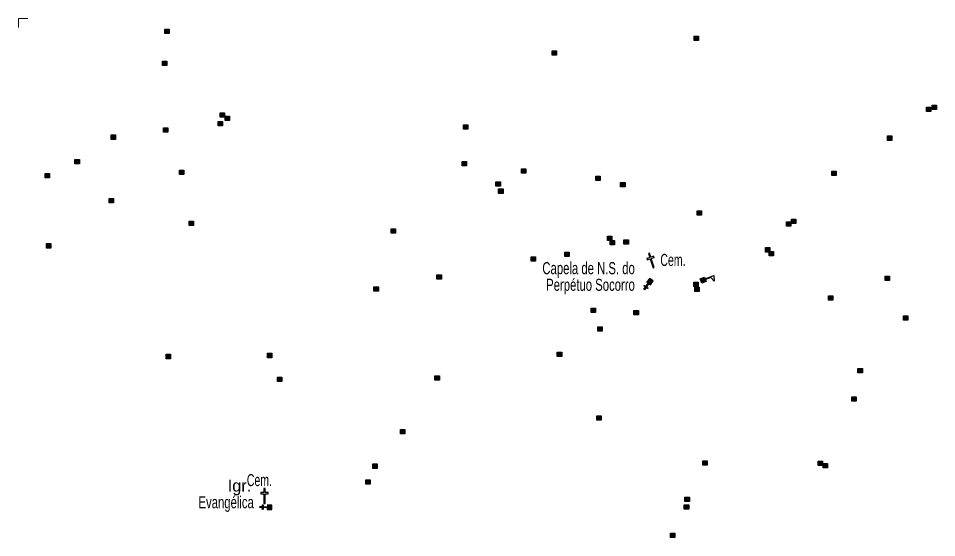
# Model space of a CAD drawing. Extents: x 647.8 to 672.9, y 6929.3 to 6957.3.
# Drawn here: x 648.17 to 654.25, y 6953.84 to 6957.28 of the extents above; entities that cross this region are included whole.
import ezdxf
from ezdxf.enums import TextEntityAlignment as Align

# ---------------------------------------------------------------- set-up
doc = ezdxf.new("R2010")
doc.units = 0
doc.header["$LTSCALE"] = 0.032
for name, color, linetype, lineweight in [('2', 7, 'Continuous', 25), ('20', 7, 'Continuous', 25), ('4', 7, 'Continuous', 25), ('6', 7, 'Continuous', 25), ('63', 7, 'Continuous', 13)]:
    doc.layers.add(name, color=color, linetype=linetype, lineweight=lineweight)
doc.layers.add('61', color=7, linetype='Continuous')

msp = doc.modelspace()

# ---------------------------------------------------------------- hatches: boundary and pattern name
at = {"layer": '2'}
for points in [[(649.1381, 6957.206), (649.1671, 6957.206), (649.1671, 6957.177), (649.1381, 6957.177)], [(652.6417, 6957.1599), (652.6707, 6957.1599), (652.6707, 6957.1309), (652.6417, 6957.1309)], [(651.7005, 6957.0634), (651.7295, 6957.0634), (651.7295, 6957.0344), (651.7005, 6957.0344)], [(649.1228, 6956.9954), (649.1518, 6956.9954), (649.1518, 6956.9664), (649.1228, 6956.9664)], [(649.5045, 6956.6531), (649.5335, 6956.6531), (649.5335, 6956.6241), (649.5045, 6956.6241)], [(654.1796, 6956.6904), (654.2086, 6956.6904), (654.2086, 6956.6614), (654.1796, 6956.6614)], [(654.2169, 6956.7036), (654.2459, 6956.7036), (654.2459, 6956.6746), (654.2169, 6956.6746)], [(649.4913, 6956.5961), (649.5203, 6956.5961), (649.5203, 6956.5671), (649.4913, 6956.5671)], [(649.5374, 6956.6312), (649.5664, 6956.6312), (649.5664, 6956.6022), (649.5374, 6956.6022)], [(649.1294, 6956.5544), (649.1584, 6956.5544), (649.1584, 6956.5254), (649.1294, 6956.5254)], [(651.1148, 6956.5742), (651.1438, 6956.5742), (651.1438, 6956.5452), (651.1148, 6956.5452)], [(648.7827, 6956.5061), (648.8117, 6956.5061), (648.8117, 6956.4771), (648.7827, 6956.4771)], [(653.9207, 6956.4996), (653.9497, 6956.4996), (653.9497, 6956.4706), (653.9207, 6956.4706)], [(648.5436, 6956.3438), (648.5726, 6956.3438), (648.5726, 6956.3148), (648.5436, 6956.3148)], [(651.106, 6956.3306), (651.135, 6956.3306), (651.135, 6956.3016), (651.106, 6956.3016)], [(651.4987, 6956.2824), (651.5277, 6956.2824), (651.5277, 6956.2534), (651.4987, 6956.2534)], [(648.3462, 6956.2517), (648.3752, 6956.2517), (648.3752, 6956.2227), (648.3462, 6956.2227)], [(649.2347, 6956.2736), (649.2637, 6956.2736), (649.2637, 6956.2446), (649.2347, 6956.2446)], [(651.9901, 6956.2341), (652.0191, 6956.2341), (652.0191, 6956.2051), (651.9901, 6956.2051)], [(653.5521, 6956.267), (653.5811, 6956.267), (653.5811, 6956.238), (653.5521, 6956.238)], [(651.3298, 6956.1968), (651.3588, 6956.1968), (651.3588, 6956.1678), (651.3298, 6956.1678)], [(652.1547, 6956.1924), (652.1837, 6956.1924), (652.1837, 6956.1634), (652.1547, 6956.1634)], [(651.3473, 6956.1485), (651.3763, 6956.1485), (651.3763, 6956.1195), (651.3473, 6956.1195)], [(648.7696, 6956.0849), (648.7986, 6956.0849), (648.7986, 6956.0559), (648.7696, 6956.0559)], [(652.6614, 6956.0038), (652.6904, 6956.0038), (652.6904, 6955.9748), (652.6614, 6955.9748)], [(649.2983, 6955.9357), (649.3273, 6955.9357), (649.3273, 6955.9067), (649.2983, 6955.9067)], [(653.2516, 6955.9314), (653.2806, 6955.9314), (653.2806, 6955.9024), (653.2516, 6955.9024)], [(653.2845, 6955.9489), (653.3135, 6955.9489), (653.3135, 6955.9199), (653.2845, 6955.9199)], [(650.6365, 6955.8853), (650.6655, 6955.8853), (650.6655, 6955.8563), (650.6365, 6955.8563)], [(652.0669, 6955.837), (652.0959, 6955.837), (652.0959, 6955.808), (652.0669, 6955.808)], [(652.0845, 6955.8085), (652.1135, 6955.8085), (652.1135, 6955.7795), (652.0845, 6955.7795)], [(652.1766, 6955.8129), (652.2056, 6955.8129), (652.2056, 6955.7839), (652.1766, 6955.7839)], [(648.3549, 6955.7866), (648.3839, 6955.7866), (648.3839, 6955.7576), (648.3549, 6955.7576)], [(653.1134, 6955.7602), (653.1424, 6955.7602), (653.1424, 6955.7312), (653.1134, 6955.7312)], [(651.5623, 6955.6988), (651.5913, 6955.6988), (651.5913, 6955.6698), (651.5623, 6955.6698)], [(651.7861, 6955.7295), (651.8151, 6955.7295), (651.8151, 6955.7005), (651.7861, 6955.7005)], [(653.1375, 6955.7339), (653.1665, 6955.7339), (653.1665, 6955.7049), (653.1375, 6955.7049)], [(650.9393, 6955.5803), (650.9683, 6955.5803), (650.9683, 6955.5513), (650.9393, 6955.5513)], [(653.9054, 6955.5716), (653.9344, 6955.5716), (653.9344, 6955.5426), (653.9054, 6955.5426)], [(650.5224, 6955.5014), (650.5514, 6955.5014), (650.5514, 6955.4724), (650.5224, 6955.4724)], [(652.6395, 6955.5321), (652.6685, 6955.5321), (652.6685, 6955.5031), (652.6395, 6955.5031)], [(652.6461, 6955.4992), (652.6751, 6955.4992), (652.6751, 6955.4702), (652.6461, 6955.4702)], [(653.5302, 6955.4421), (653.5592, 6955.4421), (653.5592, 6955.4131), (653.5302, 6955.4131)], [(651.9594, 6955.3588), (651.9884, 6955.3588), (651.9884, 6955.3298), (651.9594, 6955.3298)], [(652.243, 6955.3448), (652.272, 6955.3448), (652.272, 6955.3158), (652.243, 6955.3158)], [(654.026, 6955.3083), (654.055, 6955.3083), (654.055, 6955.2793), (654.026, 6955.2793)], [(652.0033, 6955.2359), (652.0323, 6955.2359), (652.0323, 6955.2069), (652.0033, 6955.2069)], [(651.7356, 6955.0692), (651.7646, 6955.0692), (651.7646, 6955.0402), (651.7356, 6955.0402)], [(649.1469, 6955.0538), (649.1759, 6955.0538), (649.1759, 6955.0248), (649.1469, 6955.0248)], [(649.8182, 6955.0604), (649.8472, 6955.0604), (649.8472, 6955.0314), (649.8182, 6955.0314)], [(653.7255, 6954.9595), (653.7545, 6954.9595), (653.7545, 6954.9305), (653.7255, 6954.9305)], [(649.884, 6954.9024), (649.913, 6954.9024), (649.913, 6954.8734), (649.884, 6954.8734)], [(650.9261, 6954.9112), (650.9551, 6954.9112), (650.9551, 6954.8822), (650.9261, 6954.8822)], [(653.6838, 6954.773), (653.7128, 6954.773), (653.7128, 6954.744), (653.6838, 6954.744)], [(651.9967, 6954.6458), (652.0257, 6954.6458), (652.0257, 6954.6168), (651.9967, 6954.6168)], [(650.698, 6954.5558), (650.727, 6954.5558), (650.727, 6954.5268), (650.698, 6954.5268)], [(652.6987, 6954.3496), (652.7277, 6954.3496), (652.7277, 6954.3206), (652.6987, 6954.3206)], [(653.4622, 6954.3474), (653.4912, 6954.3474), (653.4912, 6954.3184), (653.4622, 6954.3184)], [(650.5137, 6954.3277), (650.5427, 6954.3277), (650.5427, 6954.2987), (650.5137, 6954.2987)], [(653.4951, 6954.332), (653.5241, 6954.332), (653.5241, 6954.303), (653.4951, 6954.303)], [(650.4676, 6954.2224), (650.4966, 6954.2224), (650.4966, 6954.1934), (650.4676, 6954.1934)], [(652.5803, 6954.1083), (652.6093, 6954.1083), (652.6093, 6954.0793), (652.5803, 6954.0793)], [(652.5759, 6954.0578), (652.6049, 6954.0578), (652.6049, 6954.0288), (652.5759, 6954.0288)], [(652.4837, 6953.8691), (652.5127, 6953.8691), (652.5127, 6953.8401), (652.4837, 6953.8401)]]:
    msp.add_hatch(color=256, dxfattribs=at).paths.add_polyline_path(points)
at = {"layer": '4'}
msp.add_hatch(color=256, dxfattribs=at).paths.add_polyline_path([(652.6812, 6955.5538), (652.7091, 6955.5649), (652.7202, 6955.537), (652.6923, 6955.5259)])
at = {"layer": '6'}
for points in [[(652.352, 6955.515), (652.3696, 6955.5393), (652.3453, 6955.5568), (652.3277, 6955.5325)], [(652.3379, 6955.5252), (652.3419, 6955.5223), (652.3258, 6955.5), (652.3359, 6955.4927), (652.333, 6955.4886), (652.3229, 6955.4959), (652.3126, 6955.4818), (652.3086, 6955.4847), (652.3188, 6955.4989), (652.3087, 6955.5062), (652.3116, 6955.5102), (652.3217, 6955.5029)], [(649.8164, 6954.0442), (649.8162, 6954.0392), (649.7888, 6954.04), (649.7884, 6954.0275), (649.7834, 6954.0277), (649.7838, 6954.0402), (649.7663, 6954.0406), (649.7664, 6954.0456), (649.7839, 6954.0452), (649.7842, 6954.0576), (649.7892, 6954.0575), (649.7889, 6954.045)], [(649.8159, 6954.0268), (649.8459, 6954.0259), (649.8467, 6954.0559), (649.8167, 6954.0567)]]:
    msp.add_hatch(color=256, dxfattribs=at).paths.add_polyline_path(points)

# ---------------------------------------------------------------- linework, layer by layer
at = {"layer": '2'}
for points in [[(649.1381, 6957.206), (649.1671, 6957.206), (649.1671, 6957.177), (649.1381, 6957.177)], [(652.6417, 6957.1599), (652.6707, 6957.1599), (652.6707, 6957.1309), (652.6417, 6957.1309)], [(651.7005, 6957.0634), (651.7295, 6957.0634), (651.7295, 6957.0344), (651.7005, 6957.0344)], [(649.1228, 6956.9954), (649.1518, 6956.9954), (649.1518, 6956.9664), (649.1228, 6956.9664)], [(649.5045, 6956.6531), (649.5335, 6956.6531), (649.5335, 6956.6241), (649.5045, 6956.6241)], [(654.1796, 6956.6904), (654.2086, 6956.6904), (654.2086, 6956.6614), (654.1796, 6956.6614)], [(654.2169, 6956.7036), (654.2459, 6956.7036), (654.2459, 6956.6746), (654.2169, 6956.6746)], [(649.4913, 6956.5961), (649.5203, 6956.5961), (649.5203, 6956.5671), (649.4913, 6956.5671)], [(649.5374, 6956.6312), (649.5664, 6956.6312), (649.5664, 6956.6022), (649.5374, 6956.6022)], [(649.1294, 6956.5544), (649.1584, 6956.5544), (649.1584, 6956.5254), (649.1294, 6956.5254)], [(651.1148, 6956.5742), (651.1438, 6956.5742), (651.1438, 6956.5452), (651.1148, 6956.5452)], [(648.7827, 6956.5061), (648.8117, 6956.5061), (648.8117, 6956.4771), (648.7827, 6956.4771)], [(653.9207, 6956.4996), (653.9497, 6956.4996), (653.9497, 6956.4706), (653.9207, 6956.4706)], [(648.5436, 6956.3438), (648.5726, 6956.3438), (648.5726, 6956.3148), (648.5436, 6956.3148)], [(651.106, 6956.3306), (651.135, 6956.3306), (651.135, 6956.3016), (651.106, 6956.3016)], [(651.4987, 6956.2824), (651.5277, 6956.2824), (651.5277, 6956.2534), (651.4987, 6956.2534)], [(648.3462, 6956.2517), (648.3752, 6956.2517), (648.3752, 6956.2227), (648.3462, 6956.2227)], [(649.2347, 6956.2736), (649.2637, 6956.2736), (649.2637, 6956.2446), (649.2347, 6956.2446)], [(651.9901, 6956.2341), (652.0191, 6956.2341), (652.0191, 6956.2051), (651.9901, 6956.2051)], [(653.5521, 6956.267), (653.5811, 6956.267), (653.5811, 6956.238), (653.5521, 6956.238)], [(651.3298, 6956.1968), (651.3588, 6956.1968), (651.3588, 6956.1678), (651.3298, 6956.1678)], [(652.1547, 6956.1924), (652.1837, 6956.1924), (652.1837, 6956.1634), (652.1547, 6956.1634)], [(651.3473, 6956.1485), (651.3763, 6956.1485), (651.3763, 6956.1195), (651.3473, 6956.1195)], [(648.7696, 6956.0849), (648.7986, 6956.0849), (648.7986, 6956.0559), (648.7696, 6956.0559)], [(652.6614, 6956.0038), (652.6904, 6956.0038), (652.6904, 6955.9748), (652.6614, 6955.9748)], [(649.2983, 6955.9357), (649.3273, 6955.9357), (649.3273, 6955.9067), (649.2983, 6955.9067)], [(653.2516, 6955.9314), (653.2806, 6955.9314), (653.2806, 6955.9024), (653.2516, 6955.9024)], [(653.2845, 6955.9489), (653.3135, 6955.9489), (653.3135, 6955.9199), (653.2845, 6955.9199)], [(650.6365, 6955.8853), (650.6655, 6955.8853), (650.6655, 6955.8563), (650.6365, 6955.8563)], [(652.0669, 6955.837), (652.0959, 6955.837), (652.0959, 6955.808), (652.0669, 6955.808)], [(652.0845, 6955.8085), (652.1135, 6955.8085), (652.1135, 6955.7795), (652.0845, 6955.7795)], [(652.1766, 6955.8129), (652.2056, 6955.8129), (652.2056, 6955.7839), (652.1766, 6955.7839)], [(648.3549, 6955.7866), (648.3839, 6955.7866), (648.3839, 6955.7576), (648.3549, 6955.7576)], [(653.1134, 6955.7602), (653.1424, 6955.7602), (653.1424, 6955.7312), (653.1134, 6955.7312)], [(651.5623, 6955.6988), (651.5913, 6955.6988), (651.5913, 6955.6698), (651.5623, 6955.6698)], [(651.7861, 6955.7295), (651.8151, 6955.7295), (651.8151, 6955.7005), (651.7861, 6955.7005)], [(653.1375, 6955.7339), (653.1665, 6955.7339), (653.1665, 6955.7049), (653.1375, 6955.7049)], [(650.9393, 6955.5803), (650.9683, 6955.5803), (650.9683, 6955.5513), (650.9393, 6955.5513)], [(653.9054, 6955.5716), (653.9344, 6955.5716), (653.9344, 6955.5426), (653.9054, 6955.5426)], [(650.5224, 6955.5014), (650.5514, 6955.5014), (650.5514, 6955.4724), (650.5224, 6955.4724)], [(652.6395, 6955.5321), (652.6685, 6955.5321), (652.6685, 6955.5031), (652.6395, 6955.5031)], [(652.6461, 6955.4992), (652.6751, 6955.4992), (652.6751, 6955.4702), (652.6461, 6955.4702)], [(653.5302, 6955.4421), (653.5592, 6955.4421), (653.5592, 6955.4131), (653.5302, 6955.4131)], [(651.9594, 6955.3588), (651.9884, 6955.3588), (651.9884, 6955.3298), (651.9594, 6955.3298)], [(652.243, 6955.3448), (652.272, 6955.3448), (652.272, 6955.3158), (652.243, 6955.3158)], [(654.026, 6955.3083), (654.055, 6955.3083), (654.055, 6955.2793), (654.026, 6955.2793)], [(652.0033, 6955.2359), (652.0323, 6955.2359), (652.0323, 6955.2069), (652.0033, 6955.2069)], [(651.7356, 6955.0692), (651.7646, 6955.0692), (651.7646, 6955.0402), (651.7356, 6955.0402)], [(649.1469, 6955.0538), (649.1759, 6955.0538), (649.1759, 6955.0248), (649.1469, 6955.0248)], [(649.8182, 6955.0604), (649.8472, 6955.0604), (649.8472, 6955.0314), (649.8182, 6955.0314)], [(653.7255, 6954.9595), (653.7545, 6954.9595), (653.7545, 6954.9305), (653.7255, 6954.9305)], [(649.884, 6954.9024), (649.913, 6954.9024), (649.913, 6954.8734), (649.884, 6954.8734)], [(650.9261, 6954.9112), (650.9551, 6954.9112), (650.9551, 6954.8822), (650.9261, 6954.8822)], [(653.6838, 6954.773), (653.7128, 6954.773), (653.7128, 6954.744), (653.6838, 6954.744)], [(651.9967, 6954.6458), (652.0257, 6954.6458), (652.0257, 6954.6168), (651.9967, 6954.6168)], [(650.698, 6954.5558), (650.727, 6954.5558), (650.727, 6954.5268), (650.698, 6954.5268)], [(652.6987, 6954.3496), (652.7277, 6954.3496), (652.7277, 6954.3206), (652.6987, 6954.3206)], [(653.4622, 6954.3474), (653.4912, 6954.3474), (653.4912, 6954.3184), (653.4622, 6954.3184)], [(650.5137, 6954.3277), (650.5427, 6954.3277), (650.5427, 6954.2987), (650.5137, 6954.2987)], [(653.4951, 6954.332), (653.5241, 6954.332), (653.5241, 6954.303), (653.4951, 6954.303)], [(650.4676, 6954.2224), (650.4966, 6954.2224), (650.4966, 6954.1934), (650.4676, 6954.1934)], [(652.5803, 6954.1083), (652.6093, 6954.1083), (652.6093, 6954.0793), (652.5803, 6954.0793)], [(652.5759, 6954.0578), (652.6049, 6954.0578), (652.6049, 6954.0288), (652.5759, 6954.0288)], [(652.4837, 6953.8691), (652.5127, 6953.8691), (652.5127, 6953.8401), (652.4837, 6953.8401)]]:
    msp.add_lwpolyline(points, close=True, dxfattribs=at)
at = {"layer": '20'}
for points in [[(652.3475, 6955.6947), (652.3285, 6955.6885), (652.3311, 6955.6805), (652.3501, 6955.6867), (652.3698, 6955.6263)], [(652.3551, 6955.6972), (652.3464, 6955.7238), (652.3388, 6955.7214), (652.3475, 6955.6947)], [(652.3577, 6955.6891), (652.3768, 6955.6953), (652.3741, 6955.7034), (652.3551, 6955.6972)], [(652.3698, 6955.6263), (652.3774, 6955.6288), (652.3577, 6955.6891)], [(649.8011, 6954.1382), (649.8011, 6954.1662), (649.7931, 6954.1662), (649.7931, 6954.1382)], [(649.7931, 6954.1382), (649.7731, 6954.1382), (649.7731, 6954.1297), (649.7931, 6954.1297), (649.7931, 6954.0662)], [(649.7931, 6954.0662), (649.8011, 6954.0662), (649.8011, 6954.1297)], [(649.8011, 6954.1297), (649.8211, 6954.1297), (649.8211, 6954.1382), (649.8011, 6954.1382)]]:
    msp.add_lwpolyline(points, dxfattribs=at)
at = {"layer": '4'}
msp.add_line((652.7137, 6955.5532), (652.7155, 6955.5486), dxfattribs=at)
for points in [[(652.6812, 6955.5538), (652.7091, 6955.5649), (652.7202, 6955.537), (652.6923, 6955.5259)], [(652.7137, 6955.5532), (652.7718, 6955.5763), (652.7731, 6955.5392), (652.7522, 6955.5632), (652.7155, 6955.5486)]]:
    msp.add_lwpolyline(points, close=True, dxfattribs=at)
at = {"layer": '6'}
for points in [[(652.352, 6955.515), (652.3696, 6955.5393), (652.3453, 6955.5568), (652.3277, 6955.5325)], [(652.3379, 6955.5252), (652.3419, 6955.5223), (652.3258, 6955.5), (652.3359, 6955.4927), (652.333, 6955.4886), (652.3229, 6955.4959), (652.3126, 6955.4818), (652.3086, 6955.4847), (652.3188, 6955.4989), (652.3087, 6955.5062), (652.3116, 6955.5102), (652.3217, 6955.5029)], [(649.8164, 6954.0442), (649.8162, 6954.0392), (649.7888, 6954.04), (649.7884, 6954.0275), (649.7834, 6954.0277), (649.7838, 6954.0402), (649.7663, 6954.0406), (649.7664, 6954.0456), (649.7839, 6954.0452), (649.7842, 6954.0576), (649.7892, 6954.0575), (649.7889, 6954.045)], [(649.8159, 6954.0268), (649.8459, 6954.0259), (649.8467, 6954.0559), (649.8167, 6954.0567)]]:
    msp.add_lwpolyline(points, close=True, dxfattribs=at)
at = {"layer": '63'}
msp.add_lwpolyline([(648.2305, 6957.2782), (648.1689, 6957.2782), (648.1689, 6957.2175)], dxfattribs=at)

# ---------------------------------------------------------------- texts
at = {"layer": '61', "width": 0.65}
msp.add_text('Cem.', height=0.08, dxfattribs=at).set_placement((652.4177, 6955.6388))
at = {"layer": '61'}
for s, width, p in [('Capela de N.S. do', 0.7, (652.2486, 6955.5842)), (' Perpétuo Socorro', 0.7, (652.2486, 6955.4742)), ('Cem.', 0.65, (649.8473, 6954.181)), ('Evangélica', 0.7, (649.7274, 6954.0346))]:
    msp.add_text(s, height=0.08, dxfattribs=dict(at, width=width)).set_placement(p, align=Align.RIGHT)
msp.add_text('       Igr.     ', height=0.08, dxfattribs=at).set_placement((649.8583, 6954.1446), align=Align.RIGHT)

doc.saveas('drawing.dxf')
